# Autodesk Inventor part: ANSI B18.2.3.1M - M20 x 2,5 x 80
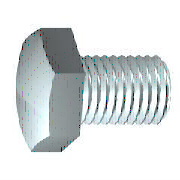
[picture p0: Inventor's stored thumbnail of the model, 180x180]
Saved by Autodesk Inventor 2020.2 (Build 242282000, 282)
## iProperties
Manager: www.cadconsulting.pl
Company: Fabian Stasiak CAD Consulting
Created: 2006-02
Part Number: ANSI B18.2.3.1M - M20 x 2,5 x 80
Material: Stal, miękka
Description: Metryczny Śruba ze łbem sześciokątnym o zmniejszonych wymiarach
Document SubType Name: Modeling
Standard: ANSI B18.2.3.1M
Designer: F.Stasiak
Standards Organization: ANSI
Language: pl-PL
Size Designation: M20 x 2,5 x 80
Categories: <MemberInstance><Categories><Category DisplayName="Mocowania" InternalName="e4da775c-781d-43d5-af7c-5136215cf5a6" Mnemonic="FSTN"><Category DisplayName="Śruby"
Density: 1 g/cm^3
Appearance: Stal
Author: F.Stasiak
Subject: Zbiór ćwiczeń. Autodesk Inventor 2020. Kurs podstawowy
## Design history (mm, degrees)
sketch "Szkic1"
  geometry: L1 (0, 13.85)-(0, 10); L2 (34, 10)-(80, 10); L3 (80, 10)-(80, 0); L4 (80, 0)-(-0.8, 0); L5 (-8.88, 0)-(104.24, 0) reference; L6 (-0.8, 0)-(-0.8, 13.85); L7 (-0.8, 13.85)-(0, 13.85); L8 (34, 10)-(32.466, 10); L9 (32.466, 10)-(0, 10); L10 (0, -1.385)-(0, 18.005) reference
  constraints: 16 end point, 2 collinear, 2 perpendicular, 1 parallel
  dimensions: "d0" = 80 distance between parallel lines of L3 L1 (= NLG); "d1" = 46 distance from line of L2.start L3 (= GEL); "d2" = 20 diameter of L2 L4 (= GD); "d9" = 0.8001 distance between parallel lines of L6 L1 (computed from SD); "d10" = 27.7 diameter of L7 L4 (= SD2); "d13" = 1.53373 distance of L2.start L8.end (computed from GAL); "d14" = 20 diameter of L9 L4 (= BDM)
revolve "Bryła" sketch "Szkic1" stored, may be unused: angle "d12" = 90 deg
sketch "Szkic2"
  geometry: L1 (0, 17.321)-(15, 8.66); L2 (15, 8.66)-(15, -8.66); L3 (15, -8.66)-(0, -17.321); L4 (0, -17.321)-(-15, -8.66); L5 (-15, -8.66)-(-15, 8.66); L6 (-15, 8.66)-(0, 17.321); 2 further points
  constraints: 12 end point, 1 coincident, 1 vertical, 11 other
  dimensions: "d11" = 30 distance between parallel lines of L5 L2 (= SW)
extrude "Głowica" join sketch "Szkic2" distance "d3" = 12.08 (= KOH - SD); taper "d4" = 0 deg
sketch "Szkic4"
  geometry: L1 (-12.88, 15)-(-12.88, 17.321); L2 (-12.88, 17.321)-(-11.54, 17.321); L3 (-11.54, 17.321)-(-12.88, 15); L4 (-14.088, 0)-(2.824, 0) reference; L5 (-0.8, 17.321)-(-12.88, 17.321) reference; L6 (-12.88, 8.66)-(-12.88, 17.321) reference
  constraints: 6 end point, 2 collinear, 1 perpendicular, 1 vertical
  dimensions: "d5" = 30 deg angle of L3 L1 (= ANG1); "d19" = 30 diameter of L1.start L4 (= SW0)
revolve "Faza1" sketch "Szkic4" stored, may be unused: angle "d21" = 90 deg
workplane "Work Plane1"
node "Bryła1"
node "Korpusy bryłowe"
node "Korpusy powierzchniowe"
feature "Gwint" dims "d15" = 46 (= GEL), "d16" = 0
chamfer "Faza2" distance "d6" = 1.53363 (= -0.5 x SPD + 0.5 x GD); stored, may be unused: second distance "d7" = 1.53373 (computed from GUL), angle "d55" = 45 deg
other parameters: "NLG" = 80 [user parameter; used in 1 equation term], "GD" = 20 (= NND) [user parameter; used in 2 equation terms], "BDM" = 20 (= NND) [user parameter; used in 1 equation term], "KOH" = 12.88 [user parameter; used in 1 equation term], "GEL" = 46 [user parameter; used in 2 equation terms], "SW" = 30 [user parameter; used in 3 equation terms], "SW0" = 30 (= SW) [user parameter; used in 1 equation term], "SPD" = 16.93275 (= NND - 1.2269 x PTC) [user parameter; used in 1 equation term], "SD2" = 27.7 (= SDH) [user parameter; used in 1 equation term], "SD" = 0.8 [user parameter; used in 3 equation terms], "ANG1" = 30 deg [user parameter; used in 1 equation term], "GAL" = 1.53363 (= 0.61345 x PTC) [user parameter; used in 1 equation term], "GUL" = 1.53363 (= 0.61345 x PTC) [user parameter; used in 1 equation term], "d8" = 0, "RR" = 0.1 [user parameter], "d57" = 0, "d58" = 0, "TPU" = 4 (computed from PTC) [user parameter], "WFT" = 0.8 (= SD) [user parameter], "GD1" = 16.93275 (= THREADDIA - 1.2269 x PTC) [user parameter], "SDH" = 27.7 [user parameter; used in 1 equation term], "TOA" = 30 deg [user parameter], "PTC" = 2.5 [user parameter; used in 5 equation terms], "KOH1" = 8.8 [user parameter], "GAL1" = 3.75 [user parameter], "RR1" = 0.8 [user parameter], "E0" = 34.65 (= 1.155 x SW) [user parameter]
